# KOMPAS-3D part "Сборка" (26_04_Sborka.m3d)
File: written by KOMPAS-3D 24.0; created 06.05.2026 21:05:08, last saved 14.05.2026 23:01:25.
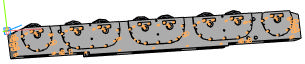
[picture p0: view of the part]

Document properties: Автор: taras; Полное имя файла: E:\test_kompas\all_v22\26_04_Sborka.m3d

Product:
- Component [detail]: Деталь  | qty 1  | pos. 2  | Масса: 261.985445; source file: C:\Users\Family\Desktop\kommpas\3.1.8 дет.45 Балка(оригинал) (1).m3d
- Component [detail]: Деталь  | qty 1  | pos. 3  | Масса: 21.934157; Организация: TMK; Автор: TMK; source file: C:\Users\Family\Desktop\kommpas\3.1.8  дет.46.2 Крышка балки (2).m3d
- Component [detail]: Деталь  | qty 1  | pos. 4  | Масса: 21.934157; Организация: TMK; Автор: TMK; source file: C:\Users\Family\Desktop\kommpas\3.1.8  дет.46.2 Крышка балки (2).m3d
- Component [detail]: Деталь  | qty 1  | pos. 5  | Масса: 9.688835; source file: C:\Users\Family\Desktop\kommpas\Крышка балки 1 окончательная (3).m3d
- Component [detail]: Деталь  | qty 1  | pos. 6  | Масса: 2.046242; Организация: TMK; Автор: TMK; source file: C:\Users\Family\Desktop\kommpas\3.1.8 дет.74 Ось кронштейна крепления опорного ролика(новый блок) (1).m3d
- Component [detail]: Деталь  | qty 1  | pos. 7  | Масса: 2.046242; Организация: TMK; Автор: TMK; source file: C:\Users\Family\Desktop\kommpas\3.1.8 дет.74 Ось кронштейна крепления опорного ролика(новый блок) (1).m3d
- Component [detail]: Деталь  | qty 1  | pos. 8  | Масса: 2.046242; Организация: TMK; Автор: TMK; source file: C:\Users\Family\Desktop\kommpas\3.1.8 дет.74 Ось кронштейна крепления опорного ролика(новый блок) (1).m3d
- Component [detail]: Деталь  | qty 1  | pos. 12  | Масса: 19.948382; Автор: taras; source file: C:\Users\Family\Desktop\kommpas\05.04 крышка200.m3d
- Component [detail]: Деталь  | qty 1  | pos. 13  | Масса: 2.046242; Организация: TMK; Автор: TMK; source file: C:\Users\Family\Desktop\kommpas\3.1.8 дет.74 Ось кронштейна крепления опорного ролика(новый блок) (1).m3d
- Component [detail]: Деталь  | qty 1  | pos. 14  | Масса: 2.046242; Организация: TMK; Автор: TMK; source file: C:\Users\Family\Desktop\kommpas\3.1.8 дет.74 Ось кронштейна крепления опорного ролика(новый блок) (1).m3d
- Component [detail]: Деталь  | qty 1  | pos. 15  | Масса: 9.688835; source file: C:\Users\Family\Desktop\kommpas\Крышка балки 1 окончательная (3).m3d
- Component [detail]: Деталь  | qty 1  | pos. 16  | Масса: 2.046242; Организация: TMK; Автор: TMK; source file: C:\Users\Family\Desktop\kommpas\3.1.8 дет.74 Ось кронштейна крепления опорного ролика(новый блок) (1).m3d
- Component [standard]: Винт М10-6gx20 ГОСТ 11738-84  | qty 31  | pos. 17  | Масса: 0.02351; Раздел спецификации: Стандартные изделия; Рассекать на разрезах: no
- Component [detail]: Деталь  | qty 1  | pos. 19  | Масса: 2.046242; Организация: TMK; Автор: TMK; source file: C:\Users\Family\Desktop\kommpas\3.1.8 дет.74 Ось кронштейна крепления опорного ролика(новый блок) (1).m3d
- Component [detail]: Деталь  | qty 1  | pos. 20  | Масса: 2.046242; Организация: TMK; Автор: TMK; source file: C:\Users\Family\Desktop\kommpas\3.1.8 дет.74 Ось кронштейна крепления опорного ролика(новый блок) (1).m3d
- Component [detail]: Деталь  | qty 1  | pos. 21  | Масса: 0.134151; Организация: TMK; Автор: TMK; source file: C:\Users\Family\Desktop\kommpas\Planka_rigelnaya (1).m3d
- Component [detail]: Деталь  | qty 1  | pos. 22  | Масса: 0.134151; Организация: TMK; Автор: TMK; source file: C:\Users\Family\Desktop\kommpas\Planka_rigelnaya (1).m3d
- Component [detail]: Деталь  | qty 1  | pos. 23  | Масса: 0.134151; Организация: TMK; Автор: TMK; source file: C:\Users\Family\Desktop\kommpas\Planka_rigelnaya (1).m3d
- Component [detail]: Деталь  | qty 1  | pos. 24  | Масса: 0.134151; Организация: TMK; Автор: TMK; source file: C:\Users\Family\Desktop\kommpas\Planka_rigelnaya (1).m3d
- Component [detail]: Деталь  | qty 1  | pos. 25  | Масса: 0.134151; Организация: TMK; Автор: TMK; source file: C:\Users\Family\Desktop\kommpas\Planka_rigelnaya (1).m3d
- Component [detail]: Деталь  | qty 1  | pos. 26  | Масса: 0.134151; Организация: TMK; Автор: TMK; source file: C:\Users\Family\Desktop\kommpas\Planka_rigelnaya (1).m3d
- Component [detail]: Деталь  | qty 1  | pos. 27  | Масса: 0.134151; Организация: TMK; Автор: TMK; source file: C:\Users\Family\Desktop\kommpas\Planka_rigelnaya (1).m3d
- Component [detail]: Деталь  | qty 1  | pos. 28  | Масса: 0.134151; Организация: TMK; Автор: TMK; source file: C:\Users\Family\Desktop\kommpas\Planka_rigelnaya (1).m3d
- Component [standard]: Подшипник 318 ГОСТ 8338-75  | qty 7  | pos. 29  | Масса: 4.954; Раздел спецификации: Стандартные изделия; additional columns: 318
- Component [standard]: Болт М16-6gx170 ГОСТ 7795-70  | qty 6  | pos. 30  | Масса: 0.2633; Раздел спецификации: Стандартные изделия; Рассекать на разрезах: no
- Component [standard]: Винт М12-6gx20 ГОСТ 11738-84  | qty 16  | pos. 31  | Масса: 0.03416; Раздел спецификации: Стандартные изделия; Рассекать на разрезах: no
- Part/product: Сборка
    Масса: 400.156123

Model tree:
1. Контекстная связь:2  (with: Грань.Вырезать элемент выдавливания:15, Контекстная связь (Деталь (1)):2, Отверстие:2, Вырезать элемент выдавливания:22, Элемент выдавливания:2, Вырезать элемент выдавливания:16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)  (labels: Скругление:2; Скругление:1; Скругление:2; Скругление:2)
     Ориентация = 2

Referenced files in C:\Users\Family\Desktop\kommpas\: 3.1.8 дет.45 Балка(оригинал) (1).m3d, 3.1.8  дет.46.2 Крышка балки (2).m3d, Крышка балки 1 окончательная (3).m3d, 05.04 крышка200.m3d, 3.1.8 дет.74 Ось кронштейна крепления опорного ролика(новый блок) (1).m3d, Planka_rigelnaya (1).m3d
Referenced files in C:\Program Files\ASCON\KOMPAS-3D v24\Libs\PolynomLib\DATA\vault\Methods\Kompas\3D\: PLib_Screw_GOST_11738_1500.m3d, PLib_Bolt_1_900.m3d
Referenced files in C:\Program Files\ASCON\KOMPAS-3D v24\Libs\PolynomLib\DATA\vault\Methods\Kompas\3D\Bearings\8338_75\: PLib_Bearing_GOST_8338_75_712.a3d
Referenced files in C:\Users\taras\Downloads\: 3.1.8  дет.46.2 Крышка балки (2).m3d, 3.1.8 дет.74 Ось кронштейна крепления опорного ролика(новый блок) (1).m3d, Крышка балки 1 окончательная (3).m3d, Planka_rigelnaya (1).m3d
Referenced files in C:\Program Files\ASCON\KOMPAS-3D v23 Study\Libs\PolynomLib\DATA\vault\Methods\Kompas\3D\: PLib_Screw_GOST_11738_1500.m3d, PLib_Bolt_1_900.m3d
Referenced files in C:\Program Files\ASCON\KOMPAS-3D v23 Study\Libs\PolynomLib\DATA\vault\Methods\Kompas\3D\Bearings\8338_75\: PLib_Bearing_GOST_8338_75_712.a3d
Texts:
  BOSimple***PART:419c87c2-70e2-98da-c2de-5eacb226740c***SHORTLOC:Root±30±20±10±80±10±GMC90[Нет;Без покрытия;Без указания материала;1,5;-;20;10]
  BOSimple***PART:61ab3e34-d848-86f0-c4aa-2b99c9f755c6***SHORTLOC:Root±Pac-16±Pac10±GMC20±GMC30±GMC10±GMC24[90;190;43]
  BOSimple***PART:9b7fe62b-1d30-3d6e-6be6-01a0e1891a36***SHORTLOC:Root±30±20±10±80±10±©{}30±©{BASE}130±190[Нет;Без покрытия;Без указания материала;170;16;22;2;-]
  BOSimple***PART:d3aa4c40-18a1-862e-ff95-3d42db175957***SHORTLOC:Root±30±20±10±80±10±GMC90[Нет;Без покрытия;Без указания материала;1,75;-;20;12]
  Деталь (1)
  Деталь (2)
  Деталь (3)
  Деталь (4)
  Деталь (5)
  Деталь (6)
  Деталь (7)
  Деталь (8)
  Подшипник 318 ГОСТ 8338-75 (1)
  Подшипник 318 ГОСТ 8338-75 (2)
  Подшипник 318 ГОСТ 8338-75 (3)
  Подшипник 318 ГОСТ 8338-75 (4)
  Подшипник 318 ГОСТ 8338-75 (5)
  Подшипник 318 ГОСТ 8338-75 (6)
  Подшипник 318 ГОСТ 8338-75 (7)
  Болт М16-6gx170 ГОСТ 7795-70 (1)
  hole1
  hole2
  Болт М16-6gx170 ГОСТ 7795-70 (2)
  Болт М16-6gx170 ГОСТ 7795-70 (3)
  Болт М16-6gx170 ГОСТ 7795-70 (4)
  Болт М16-6gx170 ГОСТ 7795-70 (5)
  Болт М16-6gx170 ГОСТ 7795-70 (6)
  Радус под головкой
